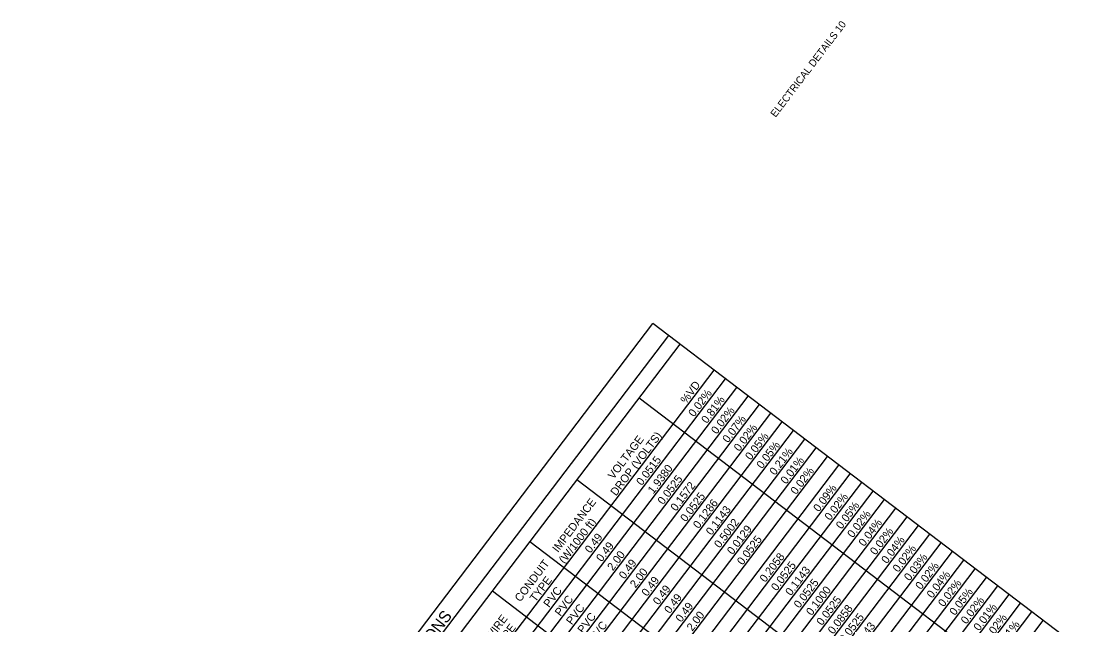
# Model space of a CAD drawing. Extents: x 1289840 to 1300285, y 220865 to 232461.
# Drawn here: x 1298779 to 1299647, y 231966 to 232461 of the extents above; entities that cross this region are included whole.
import ezdxf

# ---------------------------------------------------------------- set-up
doc = ezdxf.new("R2010")
doc.units = 0
doc.layers.add('Default', color=7, linetype='Continuous')
doc.layers.add('R_Border', color=7, linetype='Continuous')

msp = doc.modelspace()

# ---------------------------------------------------------------- linework, layer by layer
at = {"layer": 'Default'}
for p, q in [((1298779.43, 231530.95), (1299297.82, 232212.68)), ((1299646.6, 231947.46), (1299297.82, 232212.68)), ((1298792.46, 231521.04), (1299310.86, 232202.77)), ((1298801.78, 231513.96), (1299320.17, 232195.68)), ((1298829.72, 231492.71), (1299348.11, 232174.44)), ((1298839.03, 231485.63), (1299357.43, 232167.36)), ((1298848.34, 231478.55), (1299366.74, 232160.28)), ((1298857.66, 231471.46), (1299376.05, 232153.19)), ((1298866.97, 231464.38), (1299385.37, 232146.11)), ((1299584.56, 231924.83), (1299286.54, 232151.45)), ((1298876.28, 231457.3), (1299394.68, 232139.03)), ((1298885.6, 231450.22), (1299403.99, 232131.95)), ((1298894.91, 231443.14), (1299413.31, 232124.87)), ((1298904.22, 231436.05), (1299422.62, 232117.78)), ((1298913.54, 231428.97), (1299431.93, 232110.7)), ((1298922.85, 231421.89), (1299441.25, 232103.62)), ((1298932.16, 231414.81), (1299450.56, 232096.54)), ((1298941.48, 231407.73), (1299459.87, 232089.46)), ((1299533.57, 231857.77), (1299235.55, 232084.39)), ((1298950.79, 231400.64), (1299469.19, 232082.37)), ((1298960.1, 231393.56), (1299478.5, 232075.29)), ((1298969.42, 231386.48), (1299487.81, 232068.21)), ((1298978.73, 231379.4), (1299497.13, 232061.13)), ((1298988.04, 231372.32), (1299506.44, 232054.05)), ((1298997.36, 231365.24), (1299515.75, 232046.96)), ((1299006.67, 231358.15), (1299525.07, 232039.88)), ((1299015.98, 231351.07), (1299534.38, 232032.8)), ((1299494.97, 231807.01), (1299196.95, 232033.63)), ((1299025.3, 231343.99), (1299543.69, 232025.72)), ((1299034.61, 231336.91), (1299553.01, 232018.64)), ((1299043.92, 231329.83), (1299562.32, 232011.55)), ((1299053.24, 231322.74), (1299571.63, 232004.47)), ((1299062.55, 231315.66), (1299580.95, 231997.39)), ((1299071.86, 231308.58), (1299590.26, 231990.31)), ((1299464.17, 231766.5), (1299166.14, 231993.12)), ((1299081.18, 231301.5), (1299599.57, 231983.23)), ((1299090.49, 231294.42), (1299608.89, 231976.15)), ((1299099.8, 231287.33), (1299618.2, 231969.06))]:
    msp.add_line(p, q, dxfattribs=at)

# ---------------------------------------------------------------- texts
for s, height, p in [('%VD', 6.6, (1299325.1, 232146.36)), ('0.02%', 6.6, (1299331.58, 232135.55)), ('0.81%', 6.6, (1299342.19, 232130.16)), ('0.02%', 6.6, (1299350.21, 232121.39)), ('0.07%', 6.6, (1299359.52, 232114.3)), ('0.02%', 6.6, (1299368.84, 232107.22)), ('VOLTAGE ', 6.6, (1299265.55, 232084.39)), ('DROP (VOLTS)', 6.6, (1299267.61, 232070.75)), ('0.05%', 6.6, (1299378.15, 232100.14)), ('0.05%', 6.6, (1299387.46, 232093.06)), ('0.21%', 6.6, (1299398.07, 232087.67)), ('0.0515', 6.6, (1299288.78, 232079.26)), ('0.01%', 6.6, (1299407.22, 232080.38)), ('1.9380', 6.6, (1299298.24, 232072.37)), ('0.02%', 6.6, (1299415.4, 232071.81)), ('0.0525', 6.6, (1299306.28, 232063.61)), ('0.1572', 6.6, (1299316.88, 232058.22)), ('0.0525', 6.6, (1299324.9, 232049.45)), ('0.09%', 6.6, (1299434.03, 232057.65)), ('IMPEDANCE', 6.6, (1299219.94, 232024.41)), ('0.1286', 6.6, (1299335.39, 232043.92)), ('0.02%', 6.6, (1299443.34, 232050.57)), ('0.05%', 6.6, (1299452.66, 232043.49)), ('0.1143', 6.6, (1299345.95, 232038.47)), ('0.02%', 6.6, (1299461.97, 232036.4)), ('(W/1000 ft)', 6.6, (1299225.33, 232015.15)), ('0.5002', 6.6, (1299352.68, 232027.99)), ('0.04%', 6.6, (1299471.28, 232029.32)), ('0.49', 6.6, (1299246.58, 232023.77)), ('0.0129', 6.6, (1299363.27, 232022.59)), ('0.02%', 6.6, (1299480.59, 232022.24)), ('0.49', 6.6, (1299255.9, 232016.69)), ('0.0525', 6.6, (1299371.47, 232014.04)), ('0.04%', 6.6, (1299489.91, 232015.16)), ('0.02%', 6.6, (1299499.22, 232008.08)), ('2.00', 6.6, (1299265.05, 232009.4)), ('0.2058', 6.6, (1299390.09, 231999.87)), ('0.03%', 6.6, (1299508.53, 232000.99)), ('CONDUIT', 6.6, (1299189.06, 231983.8)), ('0.49', 6.6, (1299274.52, 232002.52)), ('0.0525', 6.6, (1299399.41, 231992.79)), ('0.1143', 6.6, (1299411.14, 231988.89)), ('0.02%', 6.6, (1299517.85, 231993.91)), ('TYPE', 6.6, (1299201.45, 231983.75)), ('2.00', 6.6, (1299283.68, 231995.23)), ('0.49', 6.6, (1299293.15, 231988.36)), ('0.04%', 6.6, (1299527.16, 231986.83)), ('PVC', 6.6, (1299212.67, 231979.17)), ('0.49', 6.6, (1299302.46, 231981.28)), ('0.0525', 6.6, (1299418.03, 231978.63)), ('0.1000', 6.6, (1299428.15, 231972.6)), ('0.02%', 6.6, (1299536.47, 231979.75)), ('PVC', 6.6, (1299221.98, 231972.09)), ('0.49', 6.6, (1299311.78, 231974.2)), ('0.0525', 6.6, (1299436.66, 231964.46)), ('0.05%', 6.6, (1299545.79, 231972.67)), ('0.02%', 6.6, (1299555.1, 231965.58)), ('PVC', 6.6, (1299231.29, 231965)), ('0.49', 6.6, (1299321.09, 231967.11)), ('0.0858', 6.6, (1299445.97, 231957.38)), ('0.01%', 6.6, (1299565.55, 231959.99)), ('CIRCUIT SP-3-C: VOLTAGE DROP CALCULATIONS', 9.6, (1298947, 231727.44)), ('WIRE', 6.6, (1299165.07, 231952.26)), ('PVC', 6.6, (1299240.61, 231957.92)), ('2.00', 6.6, (1299330.25, 231959.83)), ('0.0525', 6.6, (1299455.29, 231950.3)), ('0.02%', 6.6, (1299573.73, 231951.42)), ('TYPE', 6.6, (1299171.88, 231944.87)), ('PVC', 6.6, (1299249.92, 231950.84)), ('0.0643', 6.6, (1299464.51, 231943.09)), ('0.01%', 6.6, (1299584.17, 231945.83))]:
    msp.add_text(s, height=height, rotation=52.75013, dxfattribs=at).set_placement(p)
at = {"layer": 'R_Border'}
msp.add_text('ELECTRICAL DETAILS 10', height=6, rotation=52.75194, dxfattribs=at).set_placement((1299398.56, 232381.3))

doc.saveas('drawing.dxf')
